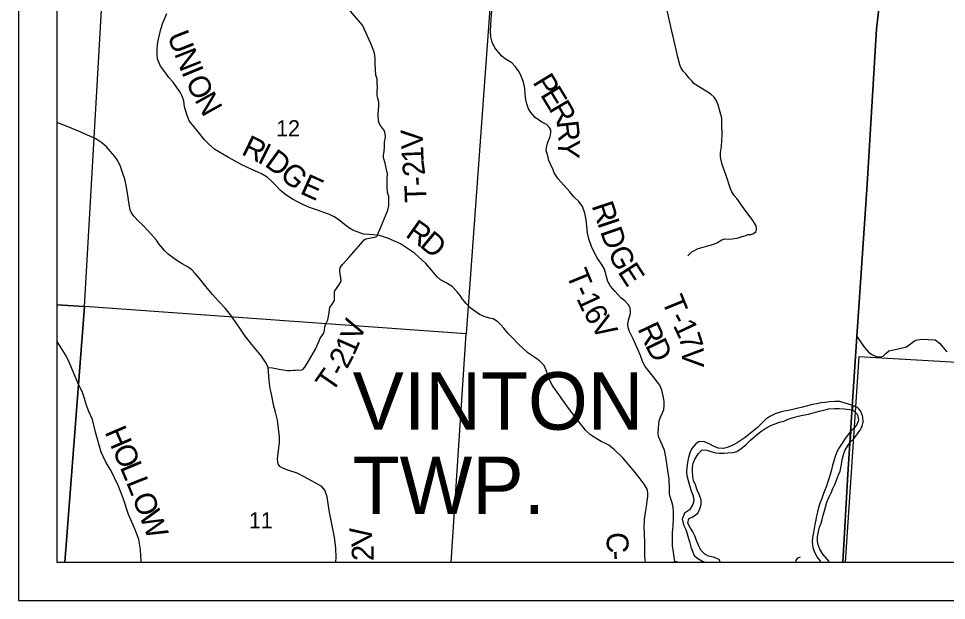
# Model space of a CAD drawing. Extents: x 0 to 34, y 0 to 22.
# Drawn here: x 2 to 4.418, y 14 to 15.517 of the extents above; entities that cross this region are included whole.
import ezdxf

# ---------------------------------------------------------------- set-up
doc = ezdxf.new("R2010")
doc.units = 0
for name, color, linetype in [('GM_X_Corporation', 7, 'Continuous'), ('GM_X_County_Road', 7, 'Continuous'), ('GM_X_County_Road_Text', 7, 'Continuous'), ('GM_X_Major_River', 7, 'Continuous'), ('GM_X_Section_Text', 7, 'Continuous'), ('GM_X_Township_Road', 7, 'Continuous'), ('GM_X_Township_Road_Text', 7, 'Continuous'), ('GM_X_Township_Text', 7, 'Continuous'), ('SH_Data', 7, 'Continuous')]:
    doc.layers.add(name, color=color, linetype=linetype)

msp = doc.modelspace()

# ---------------------------------------------------------------- linework, layer by layer
at = {"layer": 'GM_X_Corporation'}
msp.add_lwpolyline([(2.1, 20.9), (2.1, 14.1), (4.1481, 14.1), (4.1604, 14.3288), (4.1741, 14.5315), (4.1846, 14.6877), (4.2113, 15.0848), (4.2352, 15.4905), (4.2558, 15.6584), (4.2674, 15.6579), (4.2922, 15.6568), (4.4152, 15.6505), (4.4836, 15.6492), (5.4088, 15.5882), (6.2987, 15.5286), (6.3333, 15.9036), (6.368, 16.4127), (6.4323, 17.3579)], dxfattribs=at)
for points in [[(2.1, 15.7916), (2.1, 14.7705), (2.1717, 14.7661), (2.2302, 15.7835)], [(2.2302, 15.7835), (3.2411, 15.7231), (3.1659, 14.6947), (2.1717, 14.7661)], [(4.1481, 14.1), (8.9, 14.1), (8.9, 15.3662), (8.5054, 15.3919), (7.8479, 15.4342), (7.082, 15.4841), (6.7558, 15.5053), (6.7389, 15.5063), (6.2987, 15.5286), (5.4088, 15.5882), (4.4836, 15.6492), (4.4152, 15.6505), (4.2922, 15.6568), (4.2674, 15.6579), (4.2558, 15.6584), (4.2352, 15.4905), (4.2113, 15.0848), (4.1846, 14.6877), (4.1741, 14.5315), (4.1604, 14.3288)], [(2.1, 14.7705), (2.1, 14.1), (2.1207, 14.1), (2.1717, 14.7661)], [(2.1207, 14.1), (3.1276, 14.1), (3.1659, 14.6947), (2.1717, 14.7661)], [(4.1538, 14.1), (5.1819, 14.1), (5.2132, 14.5759), (4.1896, 14.6347)]]:
    msp.add_lwpolyline(points, close=True, dxfattribs=at)
at = {"layer": 'GM_X_County_Road'}
msp.add_lwpolyline([(3.6336, 14.1), (3.6319, 14.1133), (3.6314, 14.1485), (3.6306, 14.1761), (3.6301, 14.1901), (3.6307, 14.2112), (3.6334, 14.2296), (3.6358, 14.245), (3.6383, 14.2589), (3.6398, 14.2712), (3.64, 14.2809), (3.6383, 14.2901), (3.6304, 14.3033), (3.6197, 14.3168), (3.6044, 14.3367), (3.5742, 14.3718), (3.5518, 14.3932), (3.5432, 14.4006), (3.5377, 14.4044), (3.5293, 14.4093), (3.5184, 14.4146), (3.5095, 14.4199), (3.4997, 14.4253), (3.4904, 14.4319), (3.477, 14.4441), (3.4613, 14.464), (3.433, 14.5014), (3.403, 14.5429), (3.3901, 14.561), (3.384, 14.5745), (3.3793, 14.5885), (3.3747, 14.6006), (3.3691, 14.6128), (3.3571, 14.6245), (3.3475, 14.6319), (3.3273, 14.6459), (3.3025, 14.6681), (3.285, 14.6866), (3.2747, 14.6968), (3.264, 14.7095), (3.2567, 14.7185), (3.2487, 14.7263), (3.2363, 14.7343), (3.2271, 14.736), (3.2136, 14.7399), (3.201, 14.7459), (3.1887, 14.7539), (3.1768, 14.763), (3.1666, 14.7738), (3.1567, 14.7857), (3.1503, 14.7952), (3.1421, 14.8056), (3.1294, 14.8182), (3.114, 14.8279), (3.099, 14.8361), (3.0903, 14.8437), (3.0773, 14.859), (3.0614, 14.8784), (3.0319, 14.9056), (2.9954, 14.9294), (2.9637, 14.944), (2.9457, 14.9496), (2.9356, 14.952), (2.9126, 14.9542), (2.8991, 14.9545), (2.8848, 14.96), (2.8708, 14.9652), (2.8604, 14.9714), (2.8446, 14.984), (2.8346, 14.9925), (2.8226, 15.0001), (2.8101, 15.0059), (2.7956, 15.0118), (2.7767, 15.0187), (2.7585, 15.0243), (2.744, 15.0301), (2.7271, 15.039), (2.7158, 15.0454), (2.7038, 15.0519), (2.6929, 15.0597), (2.6818, 15.0693), (2.6709, 15.0806), (2.6586, 15.0937), (2.6475, 15.1031), (2.6328, 15.1119), (2.6081, 15.1237), (2.5814, 15.136), (2.547, 15.1544), (2.5118, 15.1756), (2.4945, 15.1903), (2.4849, 15.2012), (2.4678, 15.2214), (2.4564, 15.2356), (2.4449, 15.2507), (2.4389, 15.2643), (2.4326, 15.287), (2.4306, 15.3024), (2.4262, 15.3144), (2.4207, 15.325), (2.4126, 15.337), (2.4026, 15.3508), (2.3915, 15.3637), (2.381, 15.3782), (2.3701, 15.3929), (2.3655, 15.4029), (2.3622, 15.4118), (2.361, 15.4233), (2.3613, 15.4372), (2.3621, 15.4483), (2.3639, 15.46), (2.3706, 15.489), (2.3755, 15.5059), (2.386, 15.5306)], dxfattribs=at)
at = {"layer": 'GM_X_Major_River'}
for p, q in [((4.1735, 14.5085), (4.1727, 14.4966)), ((4.169, 14.4412), (4.1671, 14.4129))]:
    msp.add_line(p, q, dxfattribs=at)
for points in [[(4.1735, 14.5085), (4.1537, 14.5147), (4.1396, 14.5185), (4.1275, 14.5189), (4.113, 14.5182), (4.1009, 14.5163), (4.0914, 14.5148), (4.0804, 14.5129), (4.0686, 14.5106), (4.0557, 14.5076), (4.0424, 14.5038), (4.0276, 14.5004), (4.0173, 14.4981), (4.0056, 14.4951), (3.9949, 14.4932), (3.9843, 14.4909), (3.9714, 14.4864), (3.9573, 14.4796), (3.9474, 14.4724), (3.9379, 14.4633), (3.9258, 14.4508), (3.9159, 14.4432), (3.903, 14.4326), (3.8935, 14.425), (3.8832, 14.4178), (3.8726, 14.411), (3.8631, 14.4053), (3.849, 14.3992), (3.8369, 14.3962), (3.8228, 14.3973), (3.811, 14.4023), (3.7993, 14.4087), (3.7875, 14.4137), (3.7738, 14.4141), (3.7644, 14.4084), (3.7541, 14.3963), (3.7491, 14.3849), (3.7453, 14.3724), (3.7427, 14.3598), (3.7411, 14.3477), (3.74, 14.3356), (3.7415, 14.3257), (3.7479, 14.2999), (3.7528, 14.2858), (3.7574, 14.2726), (3.7593, 14.2593), (3.757, 14.2498), (3.7478, 14.2361), (3.7349, 14.2271), (3.7288, 14.2115), (3.733, 14.1975), (3.7383, 14.1849), (3.7421, 14.1739), (3.7455, 14.1614), (3.7489, 14.15), (3.7519, 14.1394), (3.7549, 14.1299), (3.7602, 14.117), (3.7701, 14.109), (3.78, 14.1033), (3.789, 14.1)], [(4.1671, 14.4129), (4.1769, 14.4223), (4.1803, 14.4268), (4.1834, 14.4306), (4.186, 14.4347), (4.1895, 14.4397), (4.1929, 14.4442), (4.1956, 14.4488), (4.1979, 14.4533), (4.1994, 14.4578), (4.2002, 14.4616), (4.2006, 14.4658), (4.2006, 14.4696), (4.2002, 14.4738), (4.1995, 14.4776), (4.1987, 14.4817), (4.1976, 14.4855), (4.1953, 14.4897), (4.1935, 14.4943), (4.1893, 14.4992), (4.1863, 14.5034), (4.1735, 14.5085)], [(3.8285, 14.1), (3.8252, 14.1063), (3.8104, 14.1124), (3.7978, 14.1155), (3.788, 14.1204), (3.7777, 14.1314), (3.772, 14.1439), (3.7667, 14.1565), (3.7618, 14.1682), (3.7573, 14.1789), (3.7508, 14.1887), (3.7436, 14.2016), (3.7467, 14.2138), (3.7566, 14.2179), (3.7695, 14.2278), (3.7752, 14.2388), (3.779, 14.2505), (3.7782, 14.2627), (3.7745, 14.2748), (3.768, 14.2877), (3.7635, 14.301), (3.7589, 14.3124), (3.757, 14.3234), (3.7559, 14.3367), (3.7563, 14.3477), (3.7578, 14.3583), (3.7624, 14.3682), (3.7715, 14.383), (3.781, 14.3924), (3.7932, 14.3917), (3.8034, 14.3883), (3.8171, 14.3844), (3.8266, 14.3837), (3.8376, 14.3837), (3.8482, 14.3844), (3.8623, 14.3856), (3.8718, 14.3886), (3.8832, 14.3962), (3.8946, 14.406), (3.9075, 14.4178), (3.9204, 14.4288), (3.9345, 14.4405), (3.9474, 14.4489), (3.9615, 14.4568), (3.9714, 14.4602), (3.9827, 14.4644), (3.9938, 14.4674), (4.0097, 14.4739), (4.0196, 14.4773), (4.0317, 14.4803), (4.0435, 14.4826), (4.0583, 14.486), (4.0701, 14.489), (4.0861, 14.4935), (4.0982, 14.4958), (4.1107, 14.4992), (4.1271, 14.5007), (4.1385, 14.5007), (4.1514, 14.4995), (4.1727, 14.4966)], [(4.1727, 14.4966), (4.1813, 14.4894), (4.1847, 14.4852), (4.1866, 14.4807), (4.1881, 14.4746), (4.1884, 14.4708), (4.1873, 14.467), (4.1858, 14.4628), (4.1842, 14.459), (4.1812, 14.4549), (4.1781, 14.4507), (4.169, 14.4412)], [(4.169, 14.4412), (4.1559, 14.4248), (4.1456, 14.41), (4.1372, 14.3971), (4.1319, 14.3876), (4.1266, 14.3728), (4.1239, 14.363), (4.1208, 14.3524), (4.1182, 14.3402), (4.1144, 14.3281), (4.1113, 14.3171), (4.1079, 14.3065), (4.1041, 14.2966), (4.1003, 14.286), (4.0968, 14.2765), (4.0926, 14.2655), (4.0888, 14.2549), (4.0847, 14.242), (4.082, 14.2314), (4.0793, 14.2204), (4.0774, 14.2105), (4.0751, 14.198), (4.0732, 14.1874), (4.0713, 14.1771), (4.069, 14.1642), (4.0682, 14.1524), (4.0694, 14.1384), (4.0731, 14.1282), (4.0796, 14.1141), (4.0894, 14.1012), (4.0905, 14.1)], [(4.113, 14.1), (4.1069, 14.1076), (4.0959, 14.1209), (4.0876, 14.1335), (4.0827, 14.1475), (4.0815, 14.157), (4.0815, 14.1669), (4.0842, 14.1794), (4.0873, 14.1908), (4.0914, 14.2014), (4.0941, 14.2109), (4.0964, 14.2222), (4.0998, 14.234), (4.1025, 14.2435), (4.1063, 14.2564), (4.1124, 14.27), (4.1173, 14.2807), (4.1219, 14.2917), (4.1269, 14.3023), (4.1314, 14.3137), (4.1368, 14.3273), (4.1406, 14.3368), (4.1432, 14.3497), (4.1452, 14.3603), (4.1471, 14.3698), (4.1505, 14.3835), (4.1535, 14.3929), (4.1671, 14.4129)]]:
    msp.add_lwpolyline(points, dxfattribs=at)
at = {"layer": 'GM_X_Township_Road'}
msp.add_line((3.71, 14.1028), (3.7193, 14.1), dxfattribs=at)
for points in [[(3.704, 15.4762), (3.6913, 15.5343), (3.6864, 15.5433), (3.6716, 15.5692), (3.6613, 15.5922), (3.6539, 15.6284), (3.6367, 15.6935)], [(3.7059, 14.1), (3.71, 14.1028), (3.7084, 14.1128), (3.7057, 14.1322), (3.7039, 14.1411), (3.7036, 14.1682), (3.7036, 14.1769), (3.7053, 14.1942), (3.7062, 14.2154), (3.7066, 14.2304), (3.7056, 14.2439), (3.7023, 14.2572), (3.6982, 14.2699), (3.6964, 14.2779), (3.6959, 14.2922), (3.695, 14.3151), (3.6863, 14.3742), (3.683, 14.3914), (3.6732, 14.4131), (3.6674, 14.4274), (3.6666, 14.4362), (3.6673, 14.449), (3.6681, 14.4592), (3.6694, 14.4686), (3.6727, 14.4776), (3.6781, 14.489), (3.6814, 14.498), (3.6826, 14.5095), (3.6824, 14.5199), (3.6796, 14.533), (3.6761, 14.5485), (3.6712, 14.561), (3.6503, 14.5878), (3.6326, 14.6103), (3.627, 14.621), (3.6209, 14.6383), (3.601, 14.6817), (3.5918, 14.701), (3.5891, 14.7093), (3.5877, 14.7174), (3.5886, 14.7273), (3.5914, 14.7366), (3.5944, 14.7482), (3.5947, 14.7556), (3.5932, 14.7628), (3.589, 14.7709), (3.5799, 14.7809), (3.5696, 14.7893), (3.5546, 14.8051), (3.5424, 14.8194), (3.5358, 14.8312), (3.5317, 14.8439), (3.5299, 14.8513), (3.5265, 14.8639), (3.521, 14.8743), (3.5074, 14.8934), (3.4939, 14.9202), (3.486, 14.9424), (3.4827, 14.9577), (3.4803, 14.9761), (3.4789, 14.9924), (3.4753, 15.0093), (3.4692, 15.0268), (3.4602, 15.0404), (3.4472, 15.0523), (3.4362, 15.0654), (3.4059, 15.0995), (3.3957, 15.1149), (3.3926, 15.1227), (3.3819, 15.1472), (3.3781, 15.1623), (3.3748, 15.1723), (3.3758, 15.1804), (3.3783, 15.1921), (3.3849, 15.2098), (3.3873, 15.2197), (3.387, 15.2273), (3.3829, 15.2342), (3.376, 15.2407), (3.3638, 15.2473), (3.3459, 15.259), (3.3345, 15.2717), (3.3284, 15.2819), (3.3237, 15.2972), (3.3209, 15.3101), (3.3189, 15.3351), (3.3158, 15.3509), (3.3094, 15.3672), (3.3043, 15.3781), (3.2952, 15.3911), (3.2849, 15.4013), (3.2683, 15.4124), (3.2589, 15.4187), (3.2497, 15.4305), (3.2411, 15.4409), (3.2342, 15.4555), (3.2305, 15.4693), (3.2299, 15.484), (3.2316, 15.5156), (3.2362, 15.5703)], [(2.9342, 15.3183), (2.9346, 15.3277), (2.9353, 15.3385), (2.9348, 15.3497), (2.934, 15.3586), (2.9312, 15.3698), (2.9296, 15.3987), (2.9294, 15.4136), (2.9272, 15.4272), (2.9231, 15.4393), (2.9175, 15.4518), (2.8963, 15.4998), (2.8497, 15.5545)], [(3.7441, 14.8984), (3.7546, 14.9087), (3.771, 14.9176), (3.7835, 14.9212), (3.8021, 14.9258), (3.8115, 14.9284), (3.8215, 14.9332), (3.8321, 14.9398), (3.8398, 14.9426), (3.8495, 14.9422), (3.8594, 14.9424), (3.8722, 14.9447), (3.8857, 14.9486), (3.8901, 14.95), (3.8944, 14.9514), (3.9015, 14.9537), (3.9089, 14.9542), (3.9148, 14.9569), (3.9217, 14.9616), (3.923, 14.969), (3.9215, 14.9766), (3.9131, 14.9903), (3.8906, 15.0208), (3.8712, 15.0475), (3.8649, 15.0555), (3.8589, 15.0653), (3.8554, 15.0735), (3.8436, 15.1075), (3.8329, 15.1368), (3.8301, 15.1513), (3.8288, 15.1578), (3.8286, 15.1679), (3.8312, 15.1837), (3.8335, 15.2146), (3.8325, 15.2414), (3.8321, 15.257), (3.8281, 15.273), (3.8225, 15.2921), (3.8176, 15.3039), (3.8122, 15.3118), (3.8034, 15.3202), (3.7913, 15.3279), (3.7673, 15.3421), (3.759, 15.3484), (3.7549, 15.3534), (3.7469, 15.3624), (3.7395, 15.3723), (3.7319, 15.38), (3.7263, 15.3873), (3.7227, 15.3965), (3.7181, 15.4164), (3.7044, 15.4741), (3.704, 15.4762)], [(2.9356, 14.952), (2.9382, 14.9596), (2.9459, 14.9778), (2.9531, 14.9963), (2.9618, 15.0171), (2.9652, 15.0293), (2.9649, 15.0446), (2.9647, 15.0532), (2.9615, 15.0638), (2.9605, 15.0786), (2.9605, 15.0998), (2.9611, 15.1121), (2.9586, 15.1236), (2.9553, 15.1399), (2.9511, 15.1537), (2.9506, 15.16), (2.9527, 15.1711), (2.9531, 15.1826), (2.9531, 15.1912), (2.9539, 15.196), (2.955, 15.2022), (2.9564, 15.2087), (2.9556, 15.2163), (2.9534, 15.2247), (2.9484, 15.231), (2.9432, 15.2379), (2.9391, 15.2462), (2.9382, 15.2541), (2.9372, 15.2603), (2.9369, 15.2688), (2.9388, 15.2884), (2.9391, 15.2988), (2.9357, 15.3085), (2.9341, 15.3159), (2.9342, 15.3183)], [(2.6757, 14.3589), (2.6752, 14.3618), (2.6748, 14.3694), (2.6798, 14.412), (2.6798, 14.4269), (2.6747, 14.47), (2.6697, 14.4906), (2.6651, 14.5069), (2.6584, 14.5422), (2.6556, 14.5524), (2.6534, 14.5738), (2.65, 14.6069), (2.6449, 14.6182), (2.633, 14.6368), (2.6208, 14.6518), (2.6082, 14.6675), (2.5908, 14.6891), (2.5768, 14.7096), (2.5643, 14.7274), (2.5525, 14.745), (2.5385, 14.7623), (2.5219, 14.7794), (2.5051, 14.7975), (2.4878, 14.8184), (2.4713, 14.8392), (2.4605, 14.8522), (2.4516, 14.862), (2.4416, 14.8693), (2.4267, 14.8775), (2.4122, 14.8864), (2.4, 14.8946), (2.3902, 14.9024), (2.3799, 14.9126), (2.3653, 14.93), (2.3595, 14.9389), (2.3372, 14.9645), (2.3234, 14.9781), (2.3125, 14.9889), (2.3003, 15.0021), (2.2947, 15.0101), (2.2907, 15.0185), (2.287, 15.0381), (2.2845, 15.0568), (2.2807, 15.0822), (2.2769, 15.0979), (2.2721, 15.1128), (2.2656, 15.1309), (2.2583, 15.1458), (2.2505, 15.1576), (2.2396, 15.1707), (2.2289, 15.1822), (2.2171, 15.1927), (2.2011, 15.2034), (2.1564, 15.2234), (2.1222, 15.2376), (2.1, 15.2464)], [(2.8382, 14.8497), (2.838, 14.8508), (2.8375, 14.8603), (2.8383, 14.8679), (2.8439, 14.8758), (2.8525, 14.8857), (2.861, 14.8952), (2.892, 14.9293), (2.9006, 14.94), (2.9051, 14.9427), (2.9135, 14.9442), (2.9281, 14.9475), (2.9336, 14.9491), (2.9356, 14.952)], [(2.65, 14.6069), (2.6615, 14.6065), (2.6788, 14.6033), (2.6905, 14.601), (2.7002, 14.5996), (2.7082, 14.5996), (2.7165, 14.6003), (2.7211, 14.6005), (2.727, 14.6008), (2.7337, 14.6007), (2.7408, 14.6024), (2.7457, 14.6082), (2.7523, 14.6174), (2.7612, 14.6345), (2.7735, 14.6554), (2.7832, 14.6771), (2.7857, 14.6842), (2.7951, 14.6967), (2.7972, 14.7046), (2.798, 14.7133), (2.8007, 14.7213), (2.8061, 14.7312), (2.8086, 14.7457), (2.8109, 14.7633), (2.8169, 14.7722), (2.823, 14.782), (2.8235, 14.7901), (2.823, 14.7985), (2.8234, 14.8031), (2.8243, 14.8075), (2.8345, 14.8222), (2.8403, 14.8322), (2.8398, 14.8419), (2.8382, 14.8497)], [(4.1848, 14.6872), (4.1954, 14.6715), (4.2043, 14.659), (4.2158, 14.6467), (4.2253, 14.6406), (4.2345, 14.6358), (4.2462, 14.6355), (4.2529, 14.6366), (4.2607, 14.6447), (4.2674, 14.6506), (4.2887, 14.6548), (4.3134, 14.6608), (4.3241, 14.669), (4.3375, 14.6785), (4.3526, 14.681), (4.3702, 14.6802), (4.3881, 14.6791), (4.3992, 14.671), (4.4188, 14.6484)], [(2.3196, 14.1), (2.3192, 14.1037), (2.3189, 14.1152), (2.3175, 14.1329), (2.313, 14.1588), (2.3048, 14.1821), (2.2868, 14.2237), (2.2725, 14.2666), (2.2604, 14.2975), (2.2402, 14.3399), (2.2276, 14.3601), (2.2218, 14.3717), (2.2154, 14.3868), (2.2001, 14.4385), (2.1927, 14.4713), (2.1827, 14.4927), (2.176, 14.5108), (2.1722, 14.5263), (2.1665, 14.5422), (2.1547, 14.5674), (2.1293, 14.6273), (2.1226, 14.6405), (2.1002, 14.6747), (2.1, 14.675)], [(2.8266, 14.1), (2.8275, 14.1118), (2.8268, 14.1362), (2.8234, 14.1646), (2.8092, 14.2347), (2.8043, 14.2704), (2.7982, 14.2873), (2.79, 14.2973), (2.7456, 14.3214), (2.726, 14.332), (2.7018, 14.3394), (2.6901, 14.3436), (2.6811, 14.3493), (2.6762, 14.3561), (2.6757, 14.3589)], [(4.0253, 14.1), (4.026, 14.1048), (4.0314, 14.1115), (4.0374, 14.1134)]]:
    msp.add_lwpolyline(points, dxfattribs=at)
at = {"layer": 'GM_X_Township_Text'}
msp.add_lwpolyline([(8.9, 15.3662), (8.5054, 15.3919), (7.8479, 15.4342), (7.082, 15.4841), (6.7558, 15.5053), (6.7389, 15.5063), (6.2987, 15.5286), (5.4088, 15.5882), (4.4836, 15.6492), (4.4152, 15.6505), (4.2922, 15.6568), (4.2674, 15.6579), (4.2558, 15.6584), (4.2352, 15.4905), (4.2113, 15.0848), (4.1846, 14.6877), (4.1741, 14.5315), (4.1604, 14.3288), (4.1481, 14.1)], dxfattribs=at)
at = {"layer": 'SH_Data'}
for p, q in [((2, 21), (2, 14)), ((2.1, 20.9), (2.1, 14.1)), ((2.1, 14.1), (2.1, 14.1)), ((2.1, 14.1), (4.1481, 14.1)), ((4.1481, 14.1), (8.9, 14.1)), ((2, 14), (9, 14))]:
    msp.add_line(p, q, dxfattribs=at)

# ---------------------------------------------------------------- texts
at = {"layer": 'GM_X_County_Road_Text'}
for s, rotation, p in [('U', 291.5674, (2.3865, 15.4721)), ('N', 291.6163, (2.4049, 15.4255)), ('I', 292.5335, (2.4237, 15.3781)), ('O', 295.873, (2.4341, 15.3533)), ('N', 299.1158, (2.4575, 15.3052)), ('R', 333.9621, (2.578, 15.164)), ('I', 333.3721, (2.6197, 15.1436)), ('D', 323.8572, (2.6385, 15.1344)), ('G', 317.9299, (2.6777, 15.1059)), ('E', 335.7341, (2.7308, 15.0619)), ('R', 324.8603, (3.0054, 14.9501)), ('D', 320.2439, (3.0426, 14.924)), ('C', 271.0538, (3.532, 14.1775)), ('-', 272.8317, (3.5329, 14.1289))]:
    msp.add_text(s, height=0.0568, rotation=rotation, dxfattribs=at).set_placement(p)
at = {"layer": 'GM_X_Section_Text'}
for s, p in [('12', (2.6711, 15.2101)), ('11', (2.6002, 14.1881))]:
    msp.add_text(s, height=0.04186, rotation=0, dxfattribs=at).set_placement(p)
at = {"layer": 'GM_X_Township_Road_Text'}
for s, rotation, p in [('P', 301.2751, (3.3381, 15.3513)), ('E', 301.2717, (3.358, 15.3185)), ('R', 300.3888, (3.3799, 15.2824)), ('R', 276.4458, (3.4016, 15.2481)), ('V', 91.9675, (3.0543, 15.1779)), ('Y', 267.5076, (3.4067, 15.204)), ('1', 92.2904, (3.0557, 15.143)), ('2', 97.6572, (3.0602, 15.1097)), ('-', 93.2943, (3.062, 15.0817)), ('T', 91.8346, (3.0634, 15.0377)), ('R', 288.5325, (3.4925, 15.0292)), ('I', 288.5317, (3.5073, 14.9849)), ('D', 289.0989, (3.5149, 14.9622)), ('G', 295.9401, (3.5341, 14.9081)), ('T', 292.3776, (3.426, 14.8504)), ('E', 302.9715, (3.5597, 14.8565)), ('1', 294.6608, (3.4528, 14.7876)), ('-', 294.4616, (3.4431, 14.809)), ('T', 292.1372, (3.6751, 14.7822)), ('6', 299.606, (3.4698, 14.751)), ('V', 302.2015, (3.4886, 14.7182)), ('V', 70.361, (2.8899, 14.6724)), ('R', 295.2838, (3.6117, 14.7084)), ('1', 295.385, (3.7044, 14.7171)), ('-', 297.9278, (3.6938, 14.7371)), ('7', 287.8014, (3.7187, 14.6873)), ('1', 66.1704, (2.8741, 14.6362)), ('D', 296.0196, (3.6319, 14.6655)), ('2', 61.971, (2.8557, 14.6012)), ('V', 270.1239, (3.7287, 14.6586)), ('T', 55.0761, (2.8165, 14.5392)), ('-', 62.2182, (2.8448, 14.5807)), ('H', 293.3263, (2.2237, 14.4394)), ('O', 293.31, (2.2435, 14.3935)), ('L', 292.7118, (2.2632, 14.3477)), ('L', 291.5754, (2.2795, 14.3088)), ('O', 290.834, (2.2951, 14.2694)), ('W', 291.34, (2.3131, 14.2222)), ('V', 97.6798, (2.9245, 14.1459)), ('2', 90.281, (2.9252, 14.1029))]:
    msp.add_text(s, height=0.0568, rotation=rotation, dxfattribs=at).set_placement(p)
at = {"layer": 'GM_X_Township_Text'}
for s, p in [('VINTON', (2.8704, 14.4451)), ('TWP.', (2.8704, 14.2251))]:
    msp.add_text(s, height=0.15, rotation=0, dxfattribs=at).set_placement(p)

doc.saveas('drawing.dxf')
